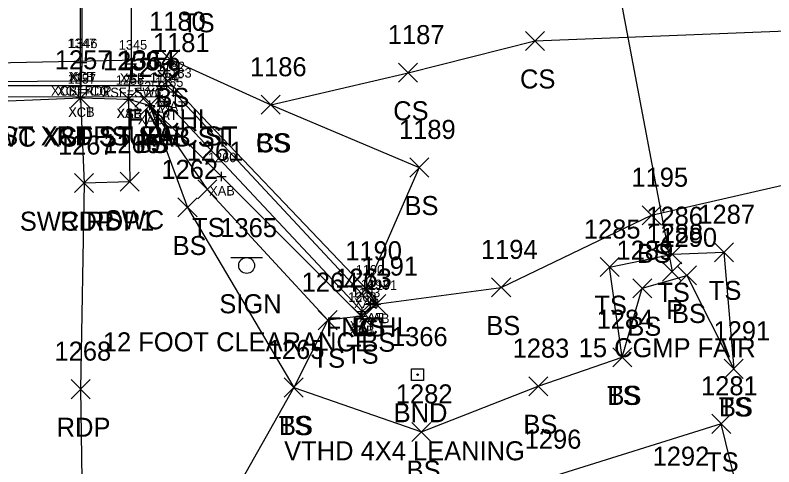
# Model space of a CAD drawing. Extents: x 49137 to 50946, y 9590 to 10709.
# Drawn here: x 49982.2 to 50061.8, y 9943.4 to 9990.9 of the extents above; entities that cross this region are included whole.
import ezdxf

# ---------------------------------------------------------------- set-up
doc = ezdxf.new("R2010")
doc.units = 0
for name, color, linetype in [('B_A', 7, 'Continuous'), ('B_C', 7, 'Continuous'), ('B_I', 7, 'Continuous'), ('B_TIC', 7, 'Continuous'), ('BDC', 7, 'Continuous'), ('BDEFAULT', 7, 'Continuous'), ('BSUBM', 7, 'Continuous'), ('D_A', 7, 'Continuous'), ('D_C', 7, 'Continuous'), ('D_I', 7, 'Continuous'), ('D_TIC', 7, 'Continuous'), ('DCP', 7, 'Continuous'), ('L_A', 7, 'Continuous'), ('L_I', 7, 'Continuous'), ('L_TIC', 7, 'Continuous'), ('LELB', 7, 'Continuous'), ('LFNC', 7, 'Continuous'), ('M_A', 7, 'Continuous'), ('M_C', 7, 'Continuous'), ('M_I', 7, 'Continuous'), ('MHBP', 7, 'Continuous'), ('P_A', 7, 'Continuous'), ('P_I', 7, 'Continuous'), ('P_TIC', 7, 'Continuous'), ('PET', 7, 'Continuous'), ('R_A', 7, 'Continuous'), ('R_I', 7, 'Continuous'), ('R_TIC', 7, 'Continuous'), ('RSW', 7, 'Continuous'), ('S_A', 7, 'Continuous'), ('S_C', 7, 'Continuous'), ('S_I', 7, 'Continuous'), ('SSGN', 7, 'Continuous'), ('U_A', 7, 'Continuous'), ('U_I', 7, 'Continuous'), ('U_TIC', 7, 'Continuous')]:
    doc.layers.add(name, color=color, linetype=linetype)

msp = doc.modelspace()

# ---------------------------------------------------------------- linework, layer by layer
at = {"layer": 'B_TIC'}
for p, q in [((49989.035, 9985.919), (49989.11, 9985.919)), ((49989.222, 9985.913), (49989.298, 9985.913)), ((49994.41, 9985.76), (49994.486, 9985.76)), ((49998.098, 9983.493), (49998.173, 9983.493)), ((49989.035, 9982.191), (49989.111, 9982.191)), ((49989.035, 9982.191), (49989.111, 9982.191)), ((49997.39, 9982.334), (49997.466, 9982.334)), ((49998.793, 9982.815), (49998.869, 9982.815)), ((49994.091, 9982.066), (49994.166, 9982.066)), ((49994.091, 9982.066), (49994.166, 9982.066)), ((49996.336, 9981.399), (49996.412, 9981.399)), ((49997.929, 9981.847), (49998.004, 9981.847)), ((50003.839, 9973.929), (50003.914, 9973.929)), ((50019.044, 9962.127), (50019.119, 9962.127)), ((50019.53, 9960.595), (50019.605, 9960.595)), ((50020.079, 9960.513), (50020.155, 9960.513)), ((50018.512, 9959.257), (50018.587, 9959.257)), ((50018.512, 9959.257), (50018.587, 9959.257)), ((50018.599, 9959.743), (50018.674, 9959.743)), ((50018.599, 9959.743), (50018.674, 9959.743))]:
    msp.add_line(p, q, dxfattribs=at)
for points in [[(49989.031, 9985.419), (49989.031, 9986.419)], [(49989.219, 9985.413), (49989.219, 9986.413)], [(49994.407, 9985.26), (49994.407, 9986.26)], [(49988.531, 9985.919), (49989.531, 9985.919)], [(49988.719, 9985.913), (49989.719, 9985.913)], [(49993.907, 9985.76), (49994.907, 9985.76)], [(49998.094, 9982.993), (49998.094, 9983.993)], [(49997.594, 9983.493), (49998.594, 9983.493)], [(49998.79, 9982.315), (49998.79, 9983.315)], [(49988.532, 9982.191), (49989.532, 9982.191)], [(49988.532, 9982.191), (49989.532, 9982.191)], [(49989.032, 9981.691), (49989.032, 9982.691)], [(49989.032, 9981.691), (49989.032, 9982.691)], [(49994.087, 9981.566), (49994.087, 9982.566)], [(49994.087, 9981.566), (49994.087, 9982.566)], [(49996.887, 9982.334), (49997.887, 9982.334)], [(49997.387, 9981.834), (49997.387, 9982.834)], [(49997.925, 9981.347), (49997.925, 9982.347)], [(49998.29, 9982.815), (49999.29, 9982.815)], [(49993.587, 9982.066), (49994.587, 9982.066)], [(49993.587, 9982.066), (49994.587, 9982.066)], [(49995.833, 9981.399), (49996.833, 9981.399)], [(49996.333, 9980.899), (49996.333, 9981.899)], [(49997.425, 9981.847), (49998.425, 9981.847)], [(50003.835, 9973.429), (50003.835, 9974.429)], [(50003.335, 9973.929), (50004.335, 9973.929)], [(50019.04, 9961.627), (50019.04, 9962.627)], [(50018.54, 9962.127), (50019.54, 9962.127)], [(50019.526, 9960.095), (50019.526, 9961.095)], [(50020.076, 9960.013), (50020.076, 9961.013)], [(50018.595, 9959.243), (50018.595, 9960.243)], [(50018.595, 9959.243), (50018.595, 9960.243)], [(50019.026, 9960.595), (50020.026, 9960.595)], [(50019.576, 9960.513), (50020.576, 9960.513)], [(50018.008, 9959.257), (50019.008, 9959.257)], [(50018.008, 9959.257), (50019.008, 9959.257)], [(50018.095, 9959.743), (50019.095, 9959.743)], [(50018.095, 9959.743), (50019.095, 9959.743)], [(50018.508, 9958.757), (50018.508, 9959.757)], [(50018.508, 9958.757), (50018.508, 9959.757)]]:
    msp.add_lwpolyline(points, dxfattribs=at)
at = {"layer": 'BDC'}
for points in [[(49989.032, 9982.191), (49989.031, 9985.919), (49988.951, 10018.034), (49989.115, 10054.273), (49989.246, 10059.027)], [(49989.032, 9982.191), (49989.219, 9985.913), (49989.145, 10017.966), (49989.217, 10054.27), (49989.246, 10059.027)]]:
    msp.add_lwpolyline(points, dxfattribs=at)
at = {"layer": 'BDEFAULT'}
msp.add_lwpolyline([(49994.087, 9982.066), (49994.407, 9985.76), (49994.334, 10018.68), (49994.089, 10054.293), (49993.801, 10059.504)], dxfattribs=at)
at = {"layer": 'BSUBM'}
for points in [[(49929.168, 9953.095), (49928.276, 9953.95), (49957.274, 9983.503), (49998.094, 9983.493), (49998.79, 9982.815), (50019.526, 9960.595), (50018.595, 9959.743)], [(49929.168, 9953.095), (49957.532, 9982.28), (49997.387, 9982.334), (49997.925, 9981.847), (50018.595, 9959.743)], [(49994.087, 9982.066), (49996.333, 9981.399), (50003.835, 9973.929), (50018.508, 9959.257)], [(50019.04, 9962.127), (50020.076, 9960.513), (50018.508, 9959.257)]]:
    msp.add_lwpolyline(points, dxfattribs=at)
at = {"layer": 'D_TIC'}
for points in [[(50050.138, 9962.938), (50052.138, 9964.938)], [(50052.138, 9962.938), (50050.138, 9964.938)]]:
    msp.add_lwpolyline(points, dxfattribs=at)
at = {"layer": 'DCP'}
msp.add_lwpolyline([(50040.524, 10020.21), (50051.138, 9963.938)], dxfattribs=at)
at = {"layer": 'L_TIC'}
for points in [[(50035.733, 9987.178), (50037.733, 9989.178)], [(50037.733, 9987.178), (50035.733, 9989.178)], [(49997.45, 9985.242), (49999.45, 9987.242)], [(49999.45, 9985.242), (49997.45, 9987.242)], [(50022.422, 9983.835), (50024.422, 9985.835)], [(50024.422, 9983.835), (50022.422, 9985.835)], [(49997.198, 9982.992), (49999.198, 9984.992)], [(49999.198, 9982.992), (49997.198, 9984.992)], [(49995.333, 9980.399), (49997.333, 9982.399)], [(49997.333, 9980.399), (49995.333, 9982.399)], [(49995.333, 9980.399), (49997.333, 9982.399)], [(49997.333, 9980.399), (49995.333, 9982.399)], [(50008.006, 9980.46), (50010.006, 9982.46)], [(50010.006, 9980.46), (50008.006, 9982.46)], [(50008.006, 9980.46), (50010.006, 9982.46)], [(50010.006, 9980.46), (50008.006, 9982.46)], [(50023.605, 9973.874), (50025.605, 9975.874)], [(50025.605, 9973.874), (50023.605, 9975.874)], [(50001.349, 9971.575), (50003.349, 9973.575)], [(50003.349, 9971.575), (50001.349, 9973.575)], [(49999.27, 9969.676), (50001.27, 9971.676)], [(50001.27, 9969.676), (49999.27, 9971.676)], [(50047.991, 9968.853), (50049.991, 9970.853)], [(50049.991, 9968.853), (50047.991, 9970.853)], [(50050.172, 9964.755), (50052.172, 9966.755)], [(50052.172, 9964.755), (50050.172, 9966.755)], [(50055.584, 9964.961), (50057.584, 9966.961)], [(50057.584, 9964.961), (50055.584, 9966.961)], [(50043.571, 9963.403), (50045.571, 9965.403)], [(50045.571, 9963.403), (50043.571, 9965.403)], [(50051.683, 9962.533), (50053.683, 9964.533)], [(50053.683, 9962.533), (50051.683, 9964.533)], [(50018.04, 9961.127), (50020.04, 9963.127)], [(50020.04, 9961.127), (50018.04, 9963.127)], [(50018.04, 9961.127), (50020.04, 9963.127)], [(50020.04, 9961.127), (50018.04, 9963.127)], [(50032.193, 9961.268), (50034.193, 9963.268)], [(50034.193, 9961.268), (50032.193, 9963.268)], [(50046.999, 9961.189), (50048.999, 9963.189)], [(50048.999, 9961.189), (50046.999, 9963.189)], [(50019.076, 9959.513), (50021.076, 9961.513)], [(50021.076, 9959.513), (50019.076, 9961.513)], [(50017.508, 9958.257), (50019.508, 9960.257)], [(50019.508, 9958.257), (50017.508, 9960.257)], [(50013.986, 9957.833), (50015.986, 9959.833)], [(50015.986, 9957.833), (50013.986, 9959.833)], [(50013.986, 9957.833), (50015.986, 9959.833)], [(50015.986, 9957.833), (50013.986, 9959.833)], [(50044.906, 9953.927), (50046.906, 9955.927)], [(50046.906, 9953.927), (50044.906, 9955.927)], [(50044.906, 9953.927), (50046.906, 9955.927)], [(50046.906, 9953.927), (50044.906, 9955.927)], [(50056.609, 9952.717), (50058.609, 9954.717)], [(50058.609, 9952.717), (50056.609, 9954.717)], [(50056.609, 9952.717), (50058.609, 9954.717)], [(50058.609, 9952.717), (50056.609, 9954.717)], [(50010.428, 9950.756), (50012.428, 9952.756)], [(50012.428, 9950.756), (50010.428, 9952.756)], [(50010.428, 9950.756), (50012.428, 9952.756)], [(50012.428, 9950.756), (50010.428, 9952.756)], [(50036.088, 9950.893), (50038.088, 9952.893)], [(50038.088, 9950.893), (50036.088, 9952.893)], [(50055.3, 9946.938), (50057.3, 9948.938)], [(50057.3, 9946.938), (50055.3, 9948.938)], [(50023.829, 9946.084), (50025.829, 9948.084)], [(50025.829, 9946.084), (50023.829, 9948.084)]]:
    msp.add_lwpolyline(points, dxfattribs=at)
at = {"layer": 'LELB'}
for points in [[(50009.006, 9981.46), (50023.422, 9984.835), (50036.733, 9988.178), (50069.311, 9989.494)], [(49947.184, 9982.022), (49948.407, 9983.553), (49973.3, 9985.731), (49998.45, 9986.242), (50009.006, 9981.46), (50024.605, 9974.874), (50019.04, 9962.127)], [(49996.333, 9981.399), (50002.349, 9972.575), (50014.986, 9958.833)], [(49996.333, 9981.399), (50000.27, 9970.676), (50011.428, 9951.756), (50024.829, 9947.084), (50037.088, 9951.893), (50045.906, 9954.927), (50047.999, 9962.189), (50052.683, 9963.533), (50057.609, 9953.717)], [(50020.076, 9960.513), (50033.193, 9962.268), (50048.991, 9969.853), (50064.389, 9973.407), (50075.145, 9979.095)], [(50045.906, 9954.927), (50044.571, 9964.403), (50051.172, 9965.755), (50056.584, 9965.961), (50057.609, 9953.717)], [(50018.508, 9959.257), (50014.986, 9958.833), (50011.428, 9951.756), (49999.675, 9930.934), (50017.715, 9937.623)], [(49999.675, 9930.934), (50001.021, 9918.298), (50007.73, 9913.847), (50014.741, 9913.336), (50038.746, 9921.214), (50058.143, 9928.966), (50058.682, 9938.222), (50056.3, 9947.938), (50038.409, 9942.328), (50017.715, 9937.623)]]:
    msp.add_lwpolyline(points, dxfattribs=at)
at = {"layer": 'LFNC'}
msp.add_lwpolyline([(49928.665, 9955.307), (49957.173, 9983.862), (49998.198, 9983.992), (50019.04, 9962.127)], dxfattribs=at)
at = {"layer": 'MHBP'}
msp.add_lwpolyline([(50023.797, 9953.732), (50025.047, 9953.732), (50025.047, 9952.482), (50023.797, 9952.482)], close=True, dxfattribs=at)
msp.add_circle((50024.422, 9953.107), 0.0833, dxfattribs=at)
at = {"layer": 'P_TIC'}
for points in [[(49988.032, 9981.191), (49990.032, 9983.191)], [(49990.032, 9981.191), (49988.032, 9983.191)], [(49988.409, 9972.229), (49990.409, 9974.229)], [(49990.409, 9972.229), (49988.409, 9974.229)], [(49988.049, 9950.58), (49990.049, 9952.58)], [(49990.049, 9950.58), (49988.049, 9952.58)]]:
    msp.add_lwpolyline(points, dxfattribs=at)
at = {"layer": 'PET'}
msp.add_lwpolyline([(49941.816, 9793.282), (49956.363, 9814.791), (49966.068, 9820.113), (49965.863, 9838.808), (49966.084, 9865.003), (49966, 9911.873), (49965.713, 9947.749), (49965.491, 9981.093), (49977.216, 9981.694), (49989.032, 9982.191), (49989.409, 9973.229), (49989.049, 9951.58), (49989.551, 9915.928), (49989.549, 9904), (49989.703, 9866.374), (49989.319, 9838.09), (49989.097, 9811.286), (49967.494, 9785.273)], dxfattribs=at)
at = {"layer": 'R_TIC'}
for points in [[(49988.032, 9981.191), (49990.032, 9983.191)], [(49990.032, 9981.191), (49988.032, 9983.191)], [(49993.087, 9981.066), (49995.087, 9983.066)], [(49995.087, 9981.066), (49993.087, 9983.066)], [(49988.409, 9972.229), (49990.409, 9974.229)], [(49990.409, 9972.229), (49988.409, 9974.229)], [(49993.211, 9972.378), (49995.211, 9974.378)], [(49995.211, 9972.378), (49993.211, 9974.378)]]:
    msp.add_lwpolyline(points, dxfattribs=at)
at = {"layer": 'RSW'}
msp.add_lwpolyline([(49989.032, 9982.191), (49994.087, 9982.066), (49994.211, 9973.378), (49989.409, 9973.229)], dxfattribs=at)
at = {"layer": 'SSGN'}
for p, q in [((50004.827, 9965.406), (50008.16, 9965.406)), ((50006.474, 9964.573), (50006.474, 9964.573))]:
    msp.add_line(p, q, dxfattribs=at)
msp.add_circle((50006.474, 9964.573), 0.833, dxfattribs=at)
at = {"layer": 'U_TIC'}
for points in [[(49994.755, 9981.197), (49996.755, 9983.197)], [(49996.755, 9981.197), (49994.755, 9983.197)]]:
    msp.add_lwpolyline(points, dxfattribs=at)

# ---------------------------------------------------------------- texts
at = {"layer": 'B_A'}
for s, p in [('XCB', (49987.767, 9983.919)), ('XCT', (49987.939, 9983.913)), ('XSF', (49993.167, 9983.76)), ('XAT', (49996.799, 9981.493)), ('XAT', (49997.494, 9980.815)), ('XCT', (49987.752, 9980.191)), ('XCB', (49987.768, 9980.191)), ('XAB', (49992.808, 9980.066)), ('XSF', (49992.847, 9980.066)), ('XAT', (49996.092, 9980.334)), ('XAT', (49996.63, 9979.847)), ('XAB', (49995.053, 9979.399)), ('XAB', (50002.556, 9971.929)), ('XAB', (50017.761, 9960.127)), ('XAT', (50018.231, 9958.595)), ('XAB', (50018.796, 9958.513)), ('XAT', (50017.3, 9957.743)), ('XAT', (50017.3, 9957.743)), ('XAB', (50017.229, 9957.257)), ('XAB', (50017.229, 9957.257))]:
    msp.add_text(s, height=1, dxfattribs=at).set_placement(p)
at = {"layer": 'B_C'}
for s, p in [('XCB=RDP', (49985.94, 9982.419)), ('XCT=CG', (49986.585, 9982.413)), ('XSF=SWC', (49991.277, 9982.26))]:
    msp.add_text(s, height=1, dxfattribs=at).set_placement(p)
at = {"layer": 'B_I'}
for s, p in [('1347', (49987.685, 9987.419)), ('1346', (49987.845, 9987.413)), ('1345', (49993.061, 9987.26)), ('1182', (49997.031, 9984.993)), ('1257', (49987.686, 9983.691)), ('1257', (49987.686, 9983.691)), ('1258', (49992.741, 9983.566)), ('1258', (49992.741, 9983.566)), ('1184', (49996.324, 9983.834)), ('1183', (49997.727, 9984.315)), ('1259', (49994.983, 9982.899)), ('1185', (49996.862, 9983.347)), ('1260', (50002.422, 9975.429)), ('1190', (50017.934, 9963.627)), ('1192', (50018.464, 9962.095)), ('1193', (50017.532, 9961.243)), ('1193', (50017.532, 9961.243)), ('1191', (50019.296, 9962.013)), ('1263', (50017.138, 9960.757)), ('1263', (50017.138, 9960.757))]:
    msp.add_text(s, height=1, dxfattribs=at).set_placement(p)
at = {"layer": 'D_A'}
msp.add_text('P', height=2, dxfattribs=at).set_placement((50050.516, 9958.938))
at = {"layer": 'D_C'}
msp.add_text('15 CGMP FAIR', height=2, dxfattribs=at).set_placement((50041.335, 9954.938))
at = {"layer": 'D_I'}
msp.add_text('1288', height=2, dxfattribs=at).set_placement((50048.446, 9966.938))
at = {"layer": 'L_A'}
for s, p in [('TS', (49999.702, 9989.08)), ('CS', (50035.174, 9983.178)), ('BS', (49996.891, 9981.242)), ('CS', (50021.863, 9979.835)), ('FNCHL', (49993.946, 9978.992)), ('TS', (49994.742, 9976.399)), ('BS', (49994.774, 9976.399)), ('CS', (50007.447, 9976.46)), ('BS', (50007.447, 9976.46)), ('BS', (50023.046, 9969.874)), ('TS', (50000.759, 9967.575)), ('BS', (49998.711, 9965.676)), ('BS', (50047.432, 9964.853)), ('TS', (50049.581, 9960.755)), ('TS', (50054.993, 9960.961)), ('TS', (50042.98, 9959.403)), ('BS', (50051.124, 9958.533)), ('FNCHL', (50014.788, 9957.127)), ('BS', (50017.481, 9957.127)), ('BS', (50031.634, 9957.268)), ('BS', (50046.44, 9957.189)), ('BS', (50018.517, 9955.513)), ('TS', (50016.918, 9954.257)), ('TS', (50013.396, 9953.833)), ('TS', (50013.396, 9953.833)), ('TS', (50044.316, 9949.927)), ('BS', (50044.347, 9949.927)), ('TS', (50056.019, 9948.717)), ('BS', (50056.05, 9948.717)), ('TS', (50009.837, 9946.756)), ('BS', (50009.869, 9946.756)), ('BS', (50035.529, 9946.893)), ('TS', (50054.71, 9942.938)), ('BS', (50023.27, 9942.084))]:
    msp.add_text(s, height=2, dxfattribs=at).set_placement(p)
at = {"layer": 'L_I'}
for s, p in [('1180', (49996.237, 9989.242)), ('1187', (50021.297, 9987.835)), ('1181', (49996.639, 9986.992)), ('1259', (49993.632, 9984.399)), ('1259', (49993.632, 9984.399)), ('1186', (50006.825, 9984.46)), ('1186', (50006.825, 9984.46)), ('1189', (50022.472, 9977.874)), ('1261', (50000.176, 9975.575)), ('1262', (49997.53, 9973.676)), ('1195', (50046.866, 9972.853)), ('1286', (50048.424, 9968.755)), ('1287', (50053.891, 9968.961)), ('1285', (50041.878, 9967.403)), ('1290', (50049.904, 9966.533)), ('1190', (50016.828, 9965.127)), ('1190', (50016.828, 9965.127)), ('1194', (50031.068, 9965.268)), ('1289', (50045.299, 9965.189)), ('1191', (50018.517, 9963.513)), ('1264', (50012.246, 9961.833)), ('1264', (50012.246, 9961.833)), ('1263', (50015.768, 9962.257)), ('1284', (50043.214, 9957.927)), ('1284', (50043.214, 9957.927)), ('1291', (50055.483, 9956.717)), ('1291', (50055.483, 9956.717)), ('1265', (50008.688, 9954.756)), ('1265', (50008.688, 9954.756)), ('1283', (50034.396, 9954.893)), ('1281', (50054.175, 9950.938)), ('1282', (50022.136, 9950.084)), ('1296', (50035.661, 9945.328)), ('1292', (50049.088, 9943.54)), ('1292', (50049.088, 9943.54))]:
    msp.add_text(s, height=2, dxfattribs=at).set_placement(p)
at = {"layer": 'M_A'}
msp.add_text('BND', height=2, dxfattribs=at).set_placement((50021.911, 9948.107))
at = {"layer": 'M_C'}
msp.add_text('VTHD 4X4 LEANING', height=2, dxfattribs=at).set_placement((50010.415, 9944.107))
at = {"layer": 'M_I'}
msp.add_text('1366', height=2, dxfattribs=at).set_placement((50021.627, 9956.107))
at = {"layer": 'P_A'}
for p in [(49986.52, 9977.191), (49986.898, 9968.229), (49986.537, 9946.58)]:
    msp.add_text('RDP', height=2, dxfattribs=at).set_placement(p)
at = {"layer": 'P_I'}
for s, p in [('1257', (49986.339, 9985.191)), ('1267', (49986.669, 9976.229)), ('1268', (49986.309, 9954.58))]:
    msp.add_text(s, height=2, dxfattribs=at).set_placement(p)
at = {"layer": 'R_A'}
for s, p in [('RDP1 XCB ST XCT ST SWC ST', (49966.583, 9977.191)), ('SWC XSF ST XAB ST', (49978.158, 9977.066)), ('SWC RDP1', (49982.669, 9968.229)), ('SWC', (49991.574, 9968.378))]:
    msp.add_text(s, height=2, dxfattribs=at).set_placement(p)
at = {"layer": 'R_I'}
for s, p in [('1257', (49986.339, 9985.191)), ('1258', (49991.394, 9985.066)), ('1267', (49986.669, 9976.229)), ('1266', (49991.416, 9976.378))]:
    msp.add_text(s, height=2, dxfattribs=at).set_placement(p)
at = {"layer": 'S_A'}
msp.add_text('SIGN', height=2, dxfattribs=at).set_placement((50003.612, 9959.553))
at = {"layer": 'S_C'}
msp.add_text('12 FOOT CLEARANCE', height=2, dxfattribs=at).set_placement((49991.384, 9955.553))
at = {"layer": 'S_I'}
msp.add_text('1365', height=2, dxfattribs=at).set_placement((50003.714, 9967.553))
at = {"layer": 'U_A'}
msp.add_text('SUBE', height=2, dxfattribs=at).set_placement((49992.291, 9977.197))
at = {"layer": 'U_I'}
msp.add_text('1364', height=2, dxfattribs=at).set_placement((49993.015, 9985.197))

doc.saveas('drawing.dxf')
